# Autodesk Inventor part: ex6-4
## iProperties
Shininess: 64.0
Length Units: 11272
Angle Units: 11279
Time Units: 11290
Mass Units: 11286
Length Display Precision: 3
Angle Display Precision: 2
Compacted: True
Part Number: ex6-4
Document SubType Name: Modeling
Created: 2002-11
Designer: Elise Moss
Density: 0.0
Volumn: 0.0
Area: 0.0
PropertySet Name: Model Information
Control State: 0
Master: False
Checked Out: False
Author: Elise Moss
